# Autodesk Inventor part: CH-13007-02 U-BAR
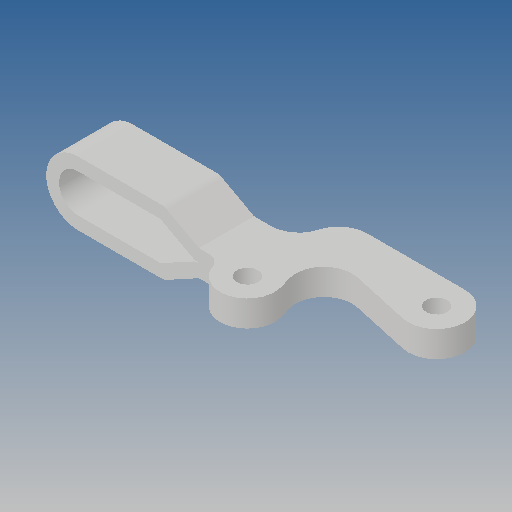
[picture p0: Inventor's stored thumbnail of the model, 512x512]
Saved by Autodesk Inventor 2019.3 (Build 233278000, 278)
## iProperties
Created: 2012-09
Part Number: CH-13007-02 U-BAR
Material: Ogólny
Document SubType Name: Modeling
Designer: CADENGINEERING4
Density: 1 g/cm^3
Appearance: Domyślna
Author: CADENGINEERING4
Revision Number: ÈÎºÎ
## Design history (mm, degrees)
feature "ÇÐ³ý-À­Éì2"
node "Bryła1"
